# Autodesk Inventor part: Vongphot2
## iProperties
Created: 2011-05
Part Number: Vongphot2
Document SubType Name: Modeling
Designer: 904Chiaki
Density: 1 g/cm^3
Author: 904Chiaki
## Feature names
1. Revolution1
